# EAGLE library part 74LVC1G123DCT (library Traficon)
CT: 26-08-2008: new package according to data from TI.
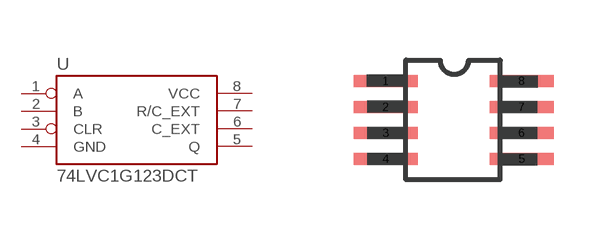
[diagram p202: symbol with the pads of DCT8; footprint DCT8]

Designator prefix U

## 74LVC1G123DCT  [DCT8]
1  A  in
2  B  in
3  CLR  in
4  GND  sup
5  Q  out
6  C_EXT  pas
7  R/C_EXT  pas
8  VCC  sup

## Footprint DCT8 (pad centres in mm)
smd 1.6 x 0.3: 1 -1.27,0.68; 2 -1.27,0.03; 3 -1.27,-0.62; 4 -1.27,-1.27; 5 2.13,-1.27; 6 2.13,-0.62; 7 2.13,0.03; 8 2.13,0.68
